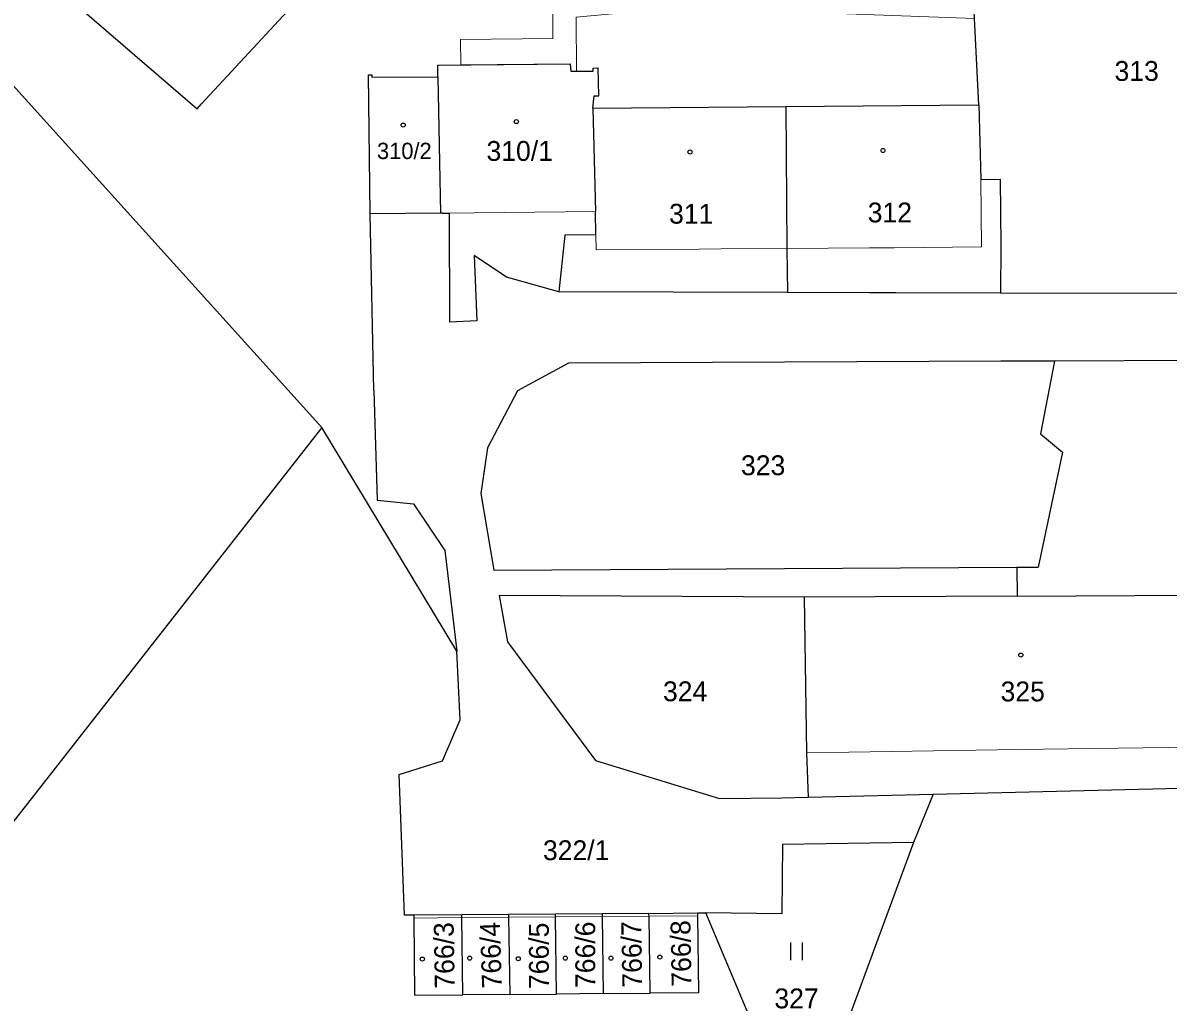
# Model space of a CAD drawing. Extents: x -727701 to -724405, y -960481 to -957284.
# Drawn here: x -727055.1 to -726957, y -958207.9 to -958124 of the extents above; entities that cross this region are included whole.
import ezdxf
from ezdxf.enums import TextEntityAlignment as Align

# ---------------------------------------------------------------- set-up
doc = ezdxf.new("R2010")
doc.units = 0
doc.header["$LTSCALE"] = 0.68
for name, color, linetype, lineweight in [('1', 7, 'Continuous', 25), ('13', 7, 'Continuous', 13), ('3', 7, 'Continuous', 25), ('4', 7, 'Continuous', 13), ('5', 7, 'Continuous', 25)]:
    doc.layers.add(name, color=color, linetype=linetype, lineweight=lineweight)
doc.layers.add('2', color=7, linetype='Continuous')

msp = doc.modelspace()

# ---------------------------------------------------------------- linework, layer by layer
at = {"layer": '1'}
for p, q in [((-727026.33, -958116.42), (-727039.81, -958130.97)), ((-727051.89, -958121.3), (-727040.17, -958131.4)), ((-727019.58, -958128.65), (-727019.57, -958127.66)), ((-727019.57, -958127.66), (-727008.25, -958127.54)), ((-727008.25, -958127.54), (-727008.18, -958128.17)), ((-727006.27, -958127.91), (-727005.84, -958127.89)), ((-727006.26, -958128.17), (-727006.27, -958127.91)), ((-727029.5, -958158.7), (-727057.02, -958128.2)), ((-727025.52, -958128.48), (-727025.22, -958128.48)), ((-727025.38, -958140.39), (-727025.52, -958128.48)), ((-727025.22, -958128.48), (-727025.22, -958128.69)), ((-727025.22, -958128.69), (-727019.58, -958128.65)), ((-727019.58, -958128.65), (-727019.33, -958140.33)), ((-727008.18, -958128.17), (-727006.26, -958128.17)), ((-727040.17, -958131.4), (-727039.81, -958130.97)), ((-727006.29, -958131.33), (-726989.77, -958131.2)), ((-727006.29, -958131.33), (-727006.06, -958140.19)), ((-726989.77, -958131.2), (-726973.24, -958131.06)), ((-726989.77, -958131.2), (-726989.67, -958143.36)), ((-726973.24, -958131.06), (-726973.06, -958137.45)), ((-726973.06, -958137.45), (-726971.42, -958137.43)), ((-726971.42, -958137.43), (-726971.35, -958143.13)), ((-727019.33, -958140.33), (-727025.38, -958140.39)), ((-727025.04, -958155.52), (-727025.38, -958140.39)), ((-727019.18, -958140.33), (-727019.33, -958140.33)), ((-727019.18, -958140.33), (-727018.57, -958140.32)), ((-727018.54, -958149.66), (-727018.57, -958140.32)), ((-727006.04, -958142.2), (-727006.06, -958140.19)), ((-727008.71, -958142.22), (-727009.2, -958147.07)), ((-727006.04, -958142.2), (-727008.71, -958142.22)), ((-726989.67, -958143.36), (-726989.64, -958147.13)), ((-726971.35, -958143.13), (-726971.39, -958147.18)), ((-727016.46, -958143.97), (-727016.24, -958149.56)), ((-727013.68, -958145.81), (-727016.46, -958143.97)), ((-727009.2, -958147.07), (-727013.68, -958145.81)), ((-726989.64, -958147.13), (-727009.2, -958147.07)), ((-726982.6, -958147.15), (-726989.64, -958147.13)), ((-726980.35, -958147.15), (-726982.6, -958147.15)), ((-726971.39, -958147.18), (-726980.35, -958147.15)), ((-726953.37, -958147.23), (-726971.39, -958147.18)), ((-727016.24, -958149.56), (-727018.54, -958149.66)), ((-727008.37, -958153.18), (-727012.75, -958155.55)), ((-726971.35, -958153.02), (-727008.37, -958153.18)), ((-726966.77, -958153), (-726971.35, -958153.02)), ((-726966.77, -958153), (-726967.96, -958159.23)), ((-726954.87, -958152.95), (-726966.77, -958153)), ((-727025.04, -958155.52), (-727024.77, -958164.91)), ((-727012.75, -958155.55), (-727015.33, -958160.44)), ((-727029.5, -958158.7), (-727100.91, -958249.86)), ((-727017.95, -958177.84), (-727029.5, -958158.7)), ((-726967.96, -958159.23), (-726966.09, -958160.79)), ((-727015.33, -958160.44), (-727015.9, -958164.34)), ((-726966.09, -958160.79), (-726968.16, -958170.65)), ((-727024.77, -958164.91), (-727021.66, -958165.22)), ((-727021.66, -958165.22), (-727018.98, -958169.22)), ((-727015.9, -958164.34), (-727014.77, -958170.91)), ((-727018.98, -958169.22), (-727017.95, -958177.84)), ((-727014.77, -958170.91), (-726969.98, -958170.66)), ((-726969.98, -958170.66), (-726968.16, -958170.65)), ((-726969.98, -958170.66), (-726969.96, -958173.13)), ((-727014.31, -958173.07), (-727013.62, -958177.05)), ((-726988.19, -958173.22), (-727014.31, -958173.07)), ((-726969.96, -958173.13), (-726951.75, -958173.03)), ((-726969.96, -958173.13), (-726988.19, -958173.22)), ((-726988.19, -958173.22), (-726988, -958186.54)), ((-727017.65, -958183.74), (-727017.95, -958177.84)), ((-727013.62, -958177.05), (-727006.07, -958187.22)), ((-727019.17, -958187.24), (-727017.65, -958183.74)), ((-726988, -958186.54), (-726987.85, -958190.36)), ((-727022.88, -958188.4), (-727019.17, -958187.24)), ((-727006.07, -958187.22), (-726995.44, -958190.47)), ((-727022.43, -958200.46), (-727022.88, -958188.4)), ((-726977.16, -958190.1), (-726951.68, -958189.46)), ((-726995.44, -958190.47), (-726990.11, -958190.42)), ((-726990.11, -958190.42), (-726987.85, -958190.36)), ((-726987.85, -958190.36), (-726977.16, -958190.1)), ((-726977.16, -958190.1), (-726978.83, -958194.22)), ((-726990.06, -958194.39), (-726990.12, -958200.34)), ((-726978.83, -958194.22), (-726990.06, -958194.39)), ((-726978.83, -958194.22), (-726986.68, -958215.48)), ((-727021.63, -958200.45), (-727022.43, -958200.46)), ((-727017.51, -958200.42), (-727021.63, -958200.45)), ((-727021.63, -958200.45), (-727021.63, -958200.7)), ((-727013.51, -958200.39), (-727017.51, -958200.42)), ((-727017.51, -958200.67), (-727017.51, -958200.42)), ((-727009.49, -958200.36), (-727013.51, -958200.39)), ((-727013.51, -958200.39), (-727013.51, -958200.64)), ((-727005.5, -958200.33), (-727009.49, -958200.36)), ((-727009.49, -958200.61), (-727009.49, -958200.36)), ((-727001.54, -958200.3), (-727005.5, -958200.33)), ((-727005.5, -958200.33), (-727005.5, -958200.58)), ((-727001.48, -958200.55), (-727001.54, -958200.3)), ((-726997.33, -958200.27), (-726996.62, -958200.26)), ((-726997.33, -958200.52), (-726997.25, -958207.11)), ((-726989.95, -958216.15), (-726996.62, -958200.26)), ((-726990.12, -958200.34), (-726996.62, -958200.26)), ((-727021.63, -958200.7), (-727021.57, -958207.3)), ((-727017.43, -958207.27), (-727017.51, -958200.67)), ((-727013.51, -958200.64), (-727013.42, -958207.24)), ((-727009.42, -958207.21), (-727009.49, -958200.61)), ((-727005.5, -958200.58), (-727005.4, -958207.17)), ((-727001.39, -958207.14), (-727001.48, -958200.55)), ((-727021.57, -958207.3), (-727017.43, -958207.27)), ((-727013.42, -958207.24), (-727017.43, -958207.27)), ((-727013.42, -958207.24), (-727009.42, -958207.21)), ((-727005.4, -958207.17), (-727009.42, -958207.21)), ((-727005.4, -958207.17), (-727001.39, -958207.14)), ((-726997.25, -958207.11), (-727001.39, -958207.14))]:
    msp.add_line(p, q, dxfattribs=at)
for points in [[(-726973.24, -958131.06), (-726973.6, -958123.65), (-726973.7, -958121.64), (-726974.09, -958113.52)], [(-727006.29, -958131.33), (-727006.19, -958130.29), (-727005.79, -958130.29), (-727005.84, -958127.89)], [(-727001.54, -958200.3), (-726997.33, -958200.27), (-726997.33, -958200.52)]]:
    msp.add_lwpolyline(points, dxfattribs=at)
at = {"layer": '13'}
msp.add_lwpolyline([(-727008.18, -958128.17), (-727007.7, -958128.17), (-727007.73, -958123.56), (-727002.18, -958123.04), (-726987.65, -958123.15), (-726973.6, -958123.65), (-726973.7, -958121.64), (-726987.35, -958121.16), (-727002.26, -958121.04), (-727009.73, -958121.74), (-727009.72, -958125.38), (-727017.64, -958125.47), (-727017.59, -958127.64), (-727008.25, -958127.54)], close=True, dxfattribs=at)
at = {"layer": '3'}
for p, q in [((-726989.341, -958204.31), (-726989.341, -958202.81)), ((-726988.34, -958204.31), (-726988.34, -958202.81))]:
    msp.add_line(p, q, dxfattribs=at)
at = {"layer": '4'}
for p, q in [((-726973, -958143.23), (-726973.06, -958137.45)), ((-727016.47, -958140.3), (-727018.57, -958140.32)), ((-727006.06, -958140.19), (-727016.47, -958140.3)), ((-727006.02, -958143.47), (-727006.04, -958142.2)), ((-726997.19, -958143.41), (-727006.02, -958143.47)), ((-726997.19, -958143.41), (-726995.35, -958143.4)), ((-726989.67, -958143.36), (-726995.35, -958143.4)), ((-726982.61, -958143.3), (-726989.67, -958143.36)), ((-726980.5, -958143.29), (-726982.61, -958143.3)), ((-726973, -958143.23), (-726980.5, -958143.29)), ((-726988, -958186.54), (-726969.88, -958186.28)), ((-726969.88, -958186.28), (-726951.57, -958186.01)), ((-727001.48, -958200.55), (-726997.33, -958200.52)), ((-727021.63, -958200.7), (-727017.51, -958200.67)), ((-727017.51, -958200.67), (-727013.51, -958200.64)), ((-727013.51, -958200.64), (-727009.49, -958200.61)), ((-727009.49, -958200.61), (-727005.5, -958200.58)), ((-727005.5, -958200.58), (-727001.48, -958200.55))]:
    msp.add_line(p, q, dxfattribs=at)
at = {"layer": '5'}
for centre in [(-727022.5368, -958132.7892), (-727012.8468, -958132.4892), (-726981.4568, -958134.9692), (-726997.9768, -958135.0992), (-726969.6468, -958178.1792), (-727020.8968, -958204.2192), (-727016.8368, -958204.1392), (-727012.6868, -958204.1892), (-727008.6568, -958204.1392), (-727004.7468, -958204.1392), (-727000.5568, -958204.0492)]:
    msp.add_circle(centre, 0.175, dxfattribs=at)

# ---------------------------------------------------------------- texts
at = {"layer": '2'}
for s, p in [('313', (-726961.62, -958129.005)), ('311', (-726999.77, -958141.235)), ('312', (-726982.76, -958141.125)), ('323', (-726993.61, -958162.775)), ('324', (-727000.29, -958182.135)), ('325', (-726971.38, -958182.145)), ('322/1', (-727010.57, -958195.745)), ('327', (-726990.75, -958208.435))]:
    msp.add_text(s, height=1.7, dxfattribs=at).set_placement(p)
for s, height, p in [('310/2', 1.4, (-727022.439, -958135.7)), ('310/1', 1.7, (-727012.56, -958135.855))]:
    msp.add_text(s, height=height, dxfattribs=at).set_placement(p, align=Align.CENTER)
for s, rotation, p in [('766/3', 91, (-727018.1746, -958203.8948)), ('766/4', 92, (-727014.1755, -958203.8497)), ('766/5', 90, (-727010.065, -958203.94)), ('766/6', 90, (-727006.095, -958203.85)), ('766/7', 91, (-727002.1146, -958203.8048)), ('766/8', 91, (-726997.8946, -958203.7248))]:
    msp.add_text(s, height=1.7, rotation=rotation, dxfattribs=at).set_placement(p, align=Align.CENTER)

doc.saveas('drawing.dxf')
